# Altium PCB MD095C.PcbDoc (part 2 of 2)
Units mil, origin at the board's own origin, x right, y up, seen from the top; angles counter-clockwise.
Board outline 4500 x 5500 mil, 6 copper layers (Top Layer, Kelvin, MidLayer2, GND, InternalPlane2, Bottom Layer); 145 components, 65 nets, 384 pads, 258 vias.
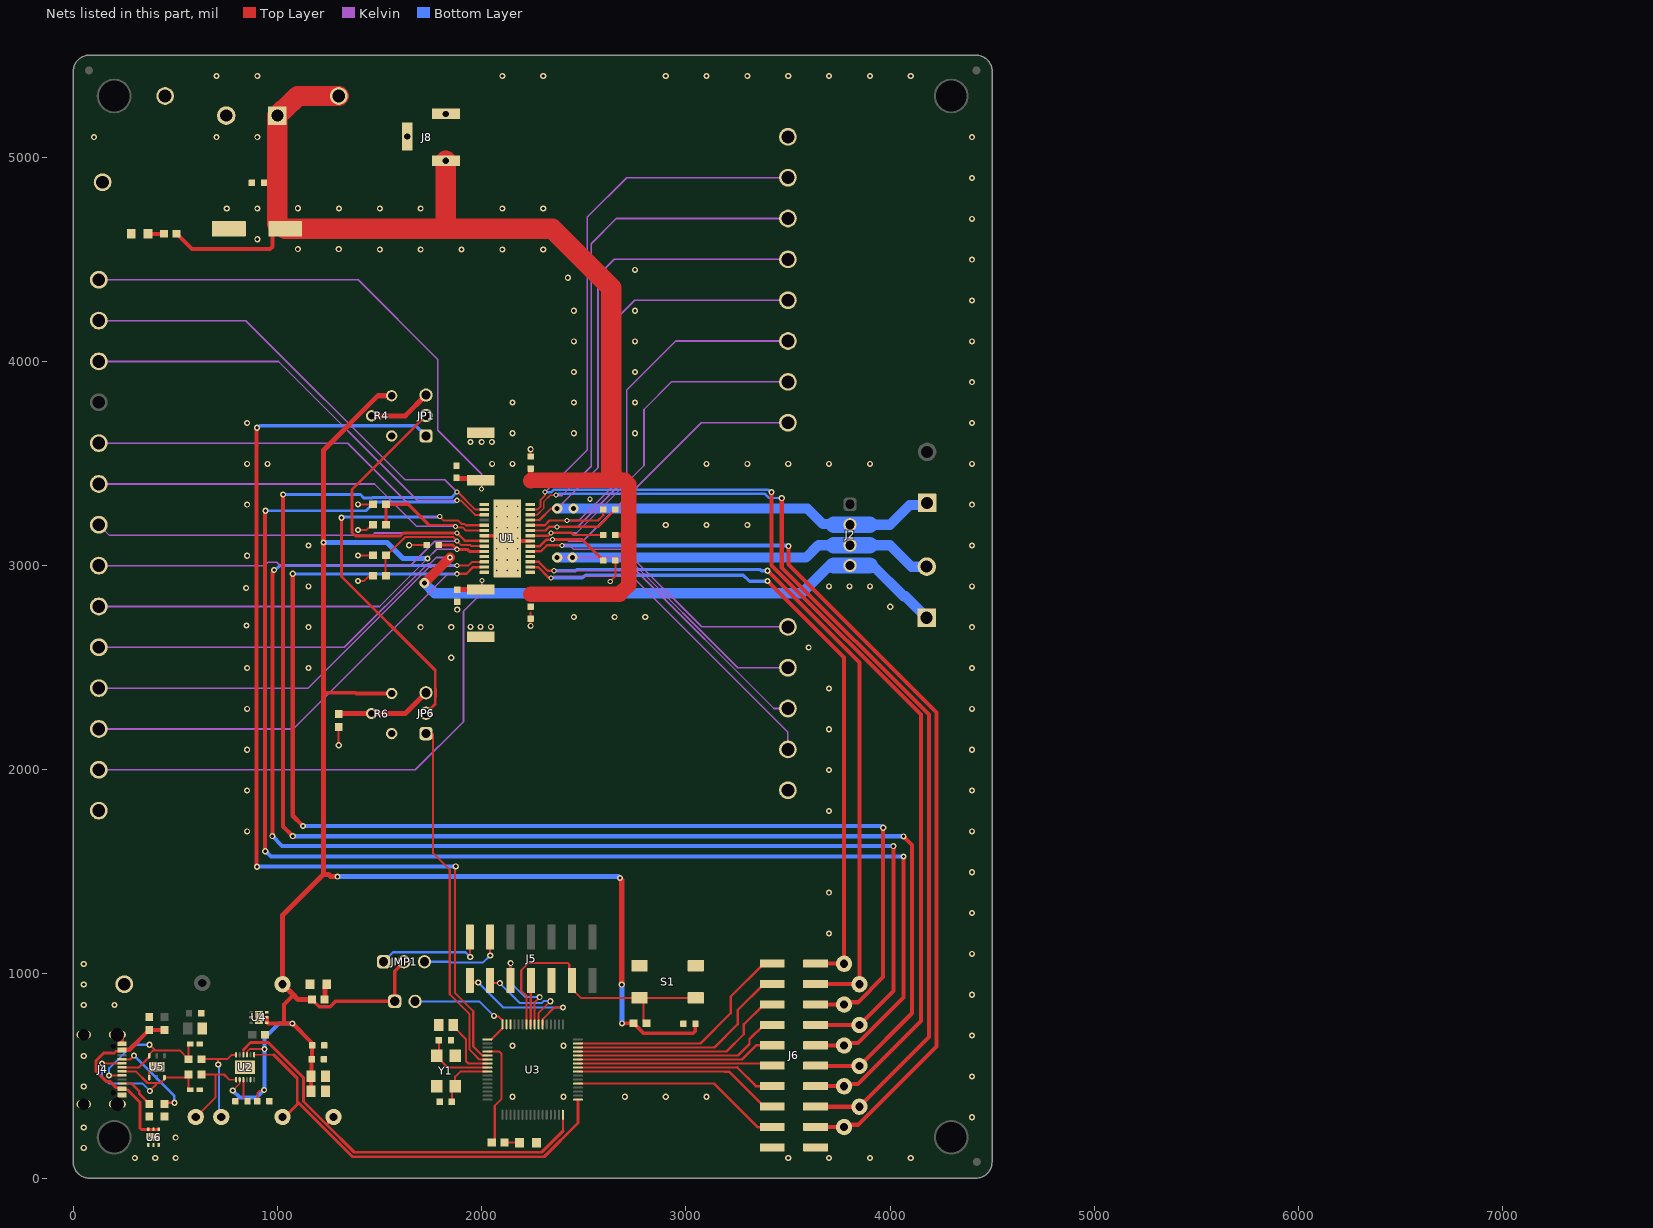
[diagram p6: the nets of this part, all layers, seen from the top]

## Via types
v1: diameter 30, hole 16, Top Layer to Bottom Layer, tented both sides, 203 vias
v2: diameter 25, hole 15, Top Layer to Bottom Layer, tented both sides, 22 vias
v3: diameter 19.68, hole 7.87, Top Layer to Bottom Layer, tented both sides, 15 vias
v4: diameter 19.68, hole 7.87, Top Layer to Bottom Layer, 12 vias
v5: diameter 50, hole 25, Top Layer to Bottom Layer, tented both sides, 6 vias

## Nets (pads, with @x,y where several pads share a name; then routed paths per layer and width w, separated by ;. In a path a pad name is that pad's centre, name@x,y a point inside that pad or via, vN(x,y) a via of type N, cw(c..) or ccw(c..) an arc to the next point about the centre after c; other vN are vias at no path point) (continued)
AOUT2: J2.2 J3.1 TP20.1 U1.25 | length 4235.3
  Top Layer w10: U1.25@2240.16,3223.23 2283.23,3223.23 2340,3280 v5(2370,3280)
  Kelvin w8: v5(2370,3280) 2570,3480 2570,4420 2650,4500 TP20.1@3500,4500
  Bottom Layer w50: v5(2370,3280) v5(2450,3280) 3595,3280 3671.74,3203.26 3720.23,3203.26 ; 3900,3200.26 4000.26,3200.26 4096.68,3296.68 4178.25,3296.68 J3.1@4192.94,3311.37
  Bottom Layer w80: 3725,3200.26 J2.2@3804.37,3200.26 3900,3200.26
BOUT1: J2.4 J7.1 TP9.1 U1.11 | length 4688.1
  Top Layer w10: U1.11@1995.91,3040 U1.11@2000,3044.09
  Top Layer w50: v5(1720,2915) v1(1845,3040)
  Kelvin w8: TP9.1@125,2600 1327.37,2600 1735.37,3008 1746.18,3008 1778.18,3040 v1(1845,3040)
  Bottom Layer w50: v5(1720,2915) 1770,2865 3567.21,2865 3702.47,3000.26 ; 3916.55,3000.26 4066.8,2850 4074.6,2850 J7.1@4179.79,2744.81
  Bottom Layer w80: 3725,3000.26 3900,3000.26
BOUT2: J2.3 J7.2 TP15.1 U1.18 | length 3232.1
  Kelvin w8: v5(2370,3040) v5(2445,3040) 2714.75,3040 3254.75,2500 TP15.1@3500,2500
  Bottom Layer w50: v5(2370,3040) v5(2445,3040) 3589,3040 3649.26,3100.26 3725,3100.26 ; 3900,3100.26 3999.74,3100.26 4105.19,2994.81 J7.2@4179.79,2994.81
  Bottom Layer w80: 3725,3100.26 J2.3@3804.37,3100.26 3900,3100.26
CC1: J4.A5 R13.1 | length 431.1
  Top Layer w10: J4.A5@238.23,581.9 278.87,581.9
  Top Layer w12: 278.87,581.9 297.02,600.04 v1(297.54,600.04) ; R13.1@446.5,364.18 451.84,369.53 v1(495.88,369.53)
  Bottom Layer w12: v1(297.54,600.04) 495.06,402.53 495.06,370.35 v1(495.88,369.53)
CC2: J4.B5 R14.1 | length 182.1
  Top Layer w10: J4.B5@238.23,463.79 284.77,463.79
  Top Layer w12: 284.77,463.79 322.19,426.37 322.19,414.48 371.5,365.17 R14.1@371.5,364.18
CP1: C7.2 TP19.1 U1.23 | length 2216.3
  Top Layer w12: U1.23@2240.16,3172.05 2312.5,3172.05 2330.46,3190 v2(2370,3190) 2370.5,3189.5 2569.03,3189.5 C7.2@2654.53,3275
  Kelvin w8: v2(2370,3190) 2470,3190 2710,3430 2710,3860 2950,4100 TP19.1@3500,4100
CP2: C7.1 TP18.1 U1.24 | length 2404.5
  Top Layer w12: U1.24@2240.16,3197.64 2309.81,3197.64 2333.07,3220.9 v2(2418.13,3220.9) 2569.9,3220.9 2595.47,3246.47 C7.1@2595.47,3275
  Kelvin w8: v2(2418.13,3220.9) 2475.9,3220.9 2650,3395 2650,4200 2750,4300 TP18.1@3500,4300
D+: C26.1 J4.A6 J4.B6 R16.1 U5.3 | length 849.9
  Top Layer w10: v1(175.52,502.41) 175.89,502.79 237.86,502.79 J4.B6@238.23,503.16 ; J4.A6@238.23,542.53 322.13,542.53 370.46,590.86 370.46,597.75 U5.3@371.7,598.98 372.93,600.22 372.93,607.11 391.38,625.56 401.15,625.56 401.35,625.76 ; v1(373.74,653.38) 401.35,625.76 ; C26.1@572.88,657.69 571.81,657.69 565,650.87 R16.1@565,582.69 564.02,582.69 520.94,625.76 401.35,625.76
  Bottom Layer w10: v1(175.52,502.41) 175.52,538.36 290.54,653.38 v1(373.74,653.38)
D-: C27.1 J4.A7 J4.B7 R15.1 U5.6 | length 927.3
  Top Layer w10: v1(140.32,561.93) 140.47,562.07 238.09,562.07 J4.B7@238.23,562.21 ; J4.A7@238.23,522.84 306.8,522.84 363.54,466.11 404.8,466.11 405,465.91 ; v1(374.97,427.47) 405,457.5 405,465.91 ; C27.1@572.88,432.69 571.81,432.69 565,439.5 R15.1@565,507.69 564.02,507.69 549.02,492.69 U5.6@446.5,492.69 445.26,491.45 445.26,484.56 426.61,465.91 405,465.91
  Bottom Layer w10: v1(140.32,561.93) 140.32,498.01 175.59,462.74 339.7,462.74 v1(374.97,427.47)
DECAY: JP6.2 TP5.1 U1.5 | length 3692.7
  Top Layer w10: v2(1795,3240) 1815,3220 1886,3220 1901.2,3204.8 1915.2,3204.8 1922.36,3197.64 U1.5@2000,3197.64
  Top Layer w14: v1(1314.1,3234.68) 1314.1,2946.9 1773.05,2487.95 1773.05,2398.59 1774.85,2396.79 1774.85,2357.62 1773.05,2355.82 1773.05,2322.68 JP6.2@1727.57,2277.2
  Kelvin w8: TP5.1@125,3600 1345,3600 1705,3240 v2(1795,3240)
  Bottom Layer w14: v1(1314.1,3234.68) 1316.76,3237.34 1792.34,3237.34 v2(1795,3240)
DIR: J6.10 TP3.1 TP41.1 U1.3 | length 9170.6
  Top Layer w10: v2(1880,3320) 1880.78,3319.22 1897.87,3319.22 1968.26,3248.82 U1.3@2000,3248.82
  Top Layer w20: v1(940,1601) 940,3268 v1(941,3269) ; J6.10@3636,651 3657,651 3657.5,650.5 3774.5,650.5 TP41.1@3775,650 3786.48,661.48 3843.5,661.48 4066.55,884.53 v1(4066.55,1575)
  Kelvin w8: TP3.1@125,4000 1005,4000 1685,3320 v2(1880,3320)
  Bottom Layer w14: v1(941,3269) 1434,3269 1476,3311 1868.02,3311 1877.02,3320 v2(1880,3320)
  Bottom Layer w20: v1(940,1601) 942.71,1601 968.71,1575 v1(4066.55,1575)
ENABLEN: J6.16 TP21.1 TP44.1 U1.26 | length 7270.5
  Top Layer w8: U1.26@2240.16,3248.82 2271.89,3248.82 2305,3281.93 2305,3313.66 2336.5,3345.16 2364.16,3345.16 v2(2365,3346)
  Top Layer w20: v1(3469.72,3330.33) 3469.72,2991.55 4190.77,2270.5 4190.77,690.77 TP44.1@3850,350 3658,350 3657,351 J6.16@3636,351
  Kelvin w8: v2(2365,3346) 2367.5,3343.5 2393.5,3343.5 2537,3487 2537,4577 2660,4700 TP21.1@3500,4700
  Bottom Layer w12: v2(2365,3346) 2367.49,3348.49 2375.42,3348.49 2378.53,3351.6 3387.67,3351.6 3408.07,3331.2 3468.85,3331.2 v1(3469.72,3330.33)
GDECAY: JP6.1 U3.6 | length 1727.8
  Top Layer w10: 1762.62,2175.63 1762.62,1591.05 1843.94,1509.73 1843.94,900.71 1941,803.65 1941,629.15 1988.94,581.21 U3.6@2028.54,581.21
GND: C1.1 C2.1 C3.1 C4.1 C5.1 C6.2 C9.2 C10.2 C11.2 C12.2 C13.2 C14.2 C15.2 C16.2 C17.1 C18.2 C19.2 C20.1 C21.1 C22.2 C23.1 C24.2 C25.1 C26.2 C27.2 C28.2 C29.1 D1.1 D10.1 D11.1 J1.2 J4.1 J4.2 J4.3 J4.4 J4.A1-B12 J4.A12-B1 J5.9 J6.19 J6.20 J8.2 J8.3 R1.2 R2.2 R4.1 R5.1 R6.1 R7.1 R13.2 R14.2 S1.1 S1.2 TP23.1 TP26.1 TP27.1 TP28.1 TP29.1 TP46.1 U1.7 U1.21 U1.29@2125.8,3133.66 U2.5 U2.13 U3.62 U3.63 U4.3 U4.5 U4.7 U5.4 U5.7@409.1,545.83 U6.1 U6.2 U6.3 U6.7@393,201 Y1.2 Y1.4 | length 1007.9
  Top Layer w10: U5.4@371.7,492.69 371.7,522.21 389.41,539.93 v3(389.41,545.83) ; v1(1300,2120) 1300,2185 ; v1(1395,2925) 1425,2925 R7.1@1450,2950 ; v1(1395,3050) C13.2@1460,3050 ; v1(1395,3175) 1437,3175 C11.2@1463,3201 ; v1(1395,3300) R5.1@1460,3300 ; v1(1645,3100) C2.1@1731.47,3100 ; U1.29@2107.28,3146.46 U1.29@2132.87,3120.87 ; v1(2240,2705) C1.1@2240,2740.47 2240,2770 ; C5.1@2240,3534.53 v1(2240,3570) ; v2(2630,2923) 2654.53,2947.53 C9.2@2654.53,3025
  Top Layer w18: U1.7@2000,3146.46 U1.29@2107.28,3146.46 ; U1.29@2132.87,3120.87 U1.21@2240.16,3120.87
  Top Layer w20: J4.1@215.99,702.76 224.66,702.76 238.23,689.2 J4.A1-B12@238.23,658.67
  other v1: 301.5,98.5 401.5,98.5 501.5,98.5 3501.5,98.5 3701.5,98.5 3901.5,98.5 4101.5,98.5 51.5,148.5 501.5,198.5 51.5,248.5 4401.5,298.5 2151.5,398.5 2401.5,398.5 2701.5,398.5 2901.5,398.5 3101.5,398.5 51.5,448.5 4401.5,498.5 51.5,598.5 2151.5,648.5 2401.5,648.5 4401.5,698.5 51.5,848.5 201.5,848.5 4401.5,898.5 51.5,948.5 51.5,1048.5 4401.5,1098.5 3701.5,1198.5 4401.5,1298.5 3701.5,1398.5 4401.5,1498.5 851.5,1698.5 4401.5,1698.5 3701.5,1798.5 851.5,1898.5 4401.5,1898.5 3701.5,1998.5 851.5,2098.5 4401.5,2098.5 3701.5,2198.5 851.5,2298.5 4401.5,2298.5 3701.5,2398.5 851.5,2498.5 1151.5,2498.5 4401.5,2498.5 1851.5,2548.5 3601.5,2598.5 1151.5,2698.5 1701.5,2698.5 1851.5,2698.5 4401.5,2698.5 1945,2700 1995,2700 2045,2700 848.4,2707.23 2451.5,2748.5 2651.5,2748.5 2801.5,2748.5 1880.79,2784.3 4001.5,2798.5 846.69,2890.63 1151.5,2898.5 3701.5,2898.5 3801.5,2898.5 3901.5,2898.5 4401.5,2898.5 851.5,3048.5 1151.5,3098.5 4401.5,3098.5 2901.5,3198.5 3101.5,3198.5 3301.5,3198.5 851.5,3298.5 4401.5,3298.5 851.5,3498.5 951.5,3498.5 2051.5,3498.5 2151.5,3498.5 3101.5,3498.5 3301.5,3498.5 3501.5,3498.5 3701.5,3498.5 3901.5,3498.5 4401.5,3498.5 1945,3605 2000,3605 2050,3605 2151.5,3648.5 2451.5,3648.5 2751.5,3648.5 851.5,3698.5 4401.5,3698.5 2151.5,3798.5 2451.5,3798.5 2751.5,3798.5 4401.5,3898.5 2451.5,3948.5 2751.5,3948.5 2451.5,4098.5 2751.5,4098.5 4401.5,4098.5 2451.5,4248.5 2751.5,4248.5 4401.5,4298.5 2422.1,4409.96 2751.5,4448.5 4401.5,4498.5 1501.5,4548.5 1701.5,4548.5 1901.5,4548.5 2101.5,4548.5 2301.5,4548.5 1100,4550 1300,4550 901.5,4598.5 4401.5,4698.5 751.5,4748.5 901.5,4748.5 1301.5,4748.5 1501.5,4748.5 1701.5,4748.5 2101.5,4748.5 2301.5,4748.5 1100,4750 4401.5,4898.5 101.5,5098.5 701.5,5098.5 901.5,5098.5 4401.5,5098.5 701.5,5398.5 901.5,5398.5 2101.5,5398.5 2301.5,5398.5 2901.5,5398.5 3101.5,5398.5 3301.5,5398.5 3501.5,5398.5 3701.5,5398.5 3901.5,5398.5 4101.5,5398.5
  other v2: 2530,3325.3
  other v3: 371.35,201 414.65,201 428.78,545.83 2074.61,2976.18 2125.8,2976.18 2176.98,2976.18 2125.8,3027.36 2125.8,3082.48 2125.8,3133.66 2125.8,3184.84 2125.8,3239.96 2074.61,3291.14 2125.8,3291.14 2176.98,3291.14
  other v4: 909.39,765.94 909.39,809.24 2074.61,3027.36 2176.98,3027.36 2074.61,3082.48 2176.98,3082.48 2074.61,3133.66 2176.98,3133.66 2074.61,3184.84 2176.98,3184.84 2074.61,3239.96 2176.98,3239.96
GVREF: JP1.1 U3.5 | length 4986.5
  Top Layer w10: v1(1873.05,1527.31) 1870.63,1524.88 1870.63,906.26 1959,817.88 1959,645.1 2003.12,600.98 2028.46,600.98 U3.5@2028.54,600.9
  Top Layer w20: v1(900,1525) 897,1528 897,3672 v1(900,3675)
  Bottom Layer w15: v1(900,3675) 904.06,3675 914.06,3685 1677.76,3685 JP1.1@1727.57,3635.19
  Bottom Layer w20: v1(900,1525) 901.15,1526.15 1871.9,1526.15 v1(1873.05,1527.31)
HOME: J6.12 TP2.1 TP42.1 U1.2 | length 9275
  Top Layer w10: v2(1880,3360) 1884.04,3360 1969.63,3274.41 U1.2@2000,3274.41
  Top Layer w20: v1(1028,3348) 1028,1722 v1(1075,1675) ; J6.12@3636,551 3657,551 3658,550 TP42.1@3850,550 4107.75,807.75 4107.75,1632.25 v1(4066,1674)
  Kelvin w8: TP2.1@125,4200 845,4200 1625,3420 1820,3420 v2(1880,3360)
  Bottom Layer w14: v1(1028,3348) 1406.18,3348 1422.18,3332 1466.17,3332 1466.97,3332.8 1852.8,3332.8 v2(1880,3360)
  Bottom Layer w20: v1(1075,1675) 1075.5,1674.5 4065.5,1674.5 v1(4066,1674)
ISENA: C6.1 R1.1 TP1.1 U1.1 | length 2668.1
  Top Layer w25: C6.1@1876.74,3429.44 1879.99,3426.19 1987.67,3426.19 R1.1@1995,3418.86
  Kelvin w8: TP1.1@125,4400 1395,4400 1785.7,4009.3 1785.7,3662.3 2000.22,3447.78 v2(2000.22,3375.21)
ISENB: C10.1 R2.1 TP12.1 U1.14 | length 2727.3
  Top Layer w25: C10.1@1880.11,2882.16 1880.6,2882.65 1994.51,2882.65 R2.1@1995,2883.14
  Kelvin w8: TP12.1@125,2000 1675,2000 1911,2236 1911,2776 2001.09,2866.09 v2(2001.09,2926.97)
MSP_DIR: J6.9 U3.43 | length 980.9
  Top Layer w10: U3.43@2471.46,581.21 3275.24,581.21
  Top Layer w12: 3275.24,581.21 3344.02,650 3422.4,650 J6.9@3423.4,651
MSP_ENABLEn: J6.15 U3.40 | length 1022.8
  Top Layer w10: U3.40@2471.46,522.16 3189.92,522.16
  Top Layer w12: 3189.92,522.16 3210.91,522.16 3382.06,351 J6.15@3423.4,351
MSP_HOME: J6.11 U3.42 | length 956.3
  Top Layer w10: U3.42@2471.46,561.53 3412.87,561.53 J6.11@3423.4,551
MSP_RESETn: J6.3 U3.46 | length 1120.9
  Top Layer w10: U3.46@2471.46,640.27 3140.06,640.27
  Top Layer w12: 3140.06,640.27 3254.22,754.43 3254.22,823.16 3382.06,951 J6.3@3423.4,951
MSP_SLEEPn: J6.13 U3.41 | length 970.2
  Top Layer w10: U3.41@2491.06,541.84 2871.3,541.84 2871.61,542.16 3251.84,542.16
  Top Layer w12: 3251.84,542.16 3343,451 J6.13@3423.4,451
MSP_SRn: J6.1 U3.47 | length 1161.1
  Top Layer w10: U3.47@2471.46,659.95 3071.59,659.95
  Top Layer w12: 3071.59,659.95 3219.98,808.35 3219.98,888.92 3382.06,1051 J6.1@3423.4,1051
MSP_STEP: J6.17 U3.37 | length 1040.6
  Top Layer w10: U3.37@2471.46,463.1 3138.78,463.1
  Top Layer w12: 3138.78,463.1 3351.89,250 3422.4,250 J6.17@3423.4,251
MSP_USM0: J6.5 U3.45 | length 1075.3
  Top Layer w10: U3.45@2471.46,620.58 3199.38,620.58
  Top Layer w12: 3199.38,620.58 3283.88,705.08 3283.88,752.82 3382.06,851 J6.5@3423.4,851
MSP_USM1: J6.7 U3.44 | length 1027.8
  Top Layer w10: U3.44@2471.46,600.9 3255.27,600.9
  Top Layer w12: 3255.27,600.9 3311.82,657.45 3311.82,680.76 3382.06,751 J6.7@3423.4,751
NetC12_1: C12.1 JP6.3 R6.2 | length 469.3
  Top Layer w25: C12.1@1300,2275 1300.32,2275.32 1460.1,2275.32 R6.2@1460.42,2275 ; R6.2@1461.06,2275.64 1626,2275.64 JP6.3@1727.57,2377.2
NetC20_2: C20.2 U3.8 Y1.1 | length 355
  Top Layer w10: C20.2@1790.94,675 1790.94,611.02 Y1.1@1779.72,599.8 1779.72,595.87 1833.75,541.84 U3.8@2028.54,541.84
NetC21_2: C21.2 U3.9 Y1.3 | length 297
  Top Layer w10: C21.2@1854.53,375 1854.53,434.45 Y1.3@1870.28,450.2 1870.28,496.69 1895.74,522.16 U3.9@2028.54,522.16
NetC25_2: C25.2 U2.3 | length 113.8
  Top Layer w9: U2.3@833.06,482.34 833.06,397.19 C25.2@853.32,376.93
NetD1_2: D1.2 R3.2 | length 77.2
  Top Layer w20: D1.2@366.34,4625 R3.2@443.5,4625
NetD10_2: D10.2 R9.1 | length 73.7
  Top Layer w10: R9.1@2112.5,175 2183.32,175 D10.2@2185.32,173
NetD11_2: D11.2 R10.1 | length 78.7
  Top Layer w25: R10.1@1232.48,875 1232.48,941.14 D11.2@1241.34,950
NetJ5_2: J5.2 JMP1.1 | length 551.6
  Top Layer w12: J5.2@1942,1181 1943,1180 1943,1084 v1(1944,1083)
  Bottom Layer w12: JMP1.1@1520,1060 1566.28,1106.28 1920.61,1106.28 1943.89,1083 v1(1944,1083)
NetJ5_4: J5.4 JMP1.3 | length 429
  Top Layer w10: v1(2042,1090.75) J5.4@2042,1181
  Bottom Layer w10: JMP1.3@1720,1060 1848.05,1060 1852.85,1055.2 2006.45,1055.2 v1(2042,1090.75)
NetJP1_3: JP1.3 R4.2 | length 308.6
  Top Layer w25: R4.2@1461.06,3733.63 1626,3733.63 JP1.3@1727.57,3835.19
NetJP7_2: JP7.2 U3.1 U3.64 | length 543.3
  Top Layer w10: U3.1@2048.15,679.72 U3.64@2102.28,733.85 ; v1(2060.07,794.86) 2063.9,791.04 2084.31,791.04 U3.64@2102.28,773.06
  Bottom Layer w10: JP7.2@1674,866 1988.93,866 v1(2060.07,794.86)
P6M5: R9.2 U3.4 | length 527.9
  Top Layer w10: U3.4@2028.54,620.58 2085.29,620.58 2097.62,608.25 2097.62,388.6 2064.19,355.17 2064.19,188.7 2050.49,175 R9.2@2049.5,175
RCA: C11.1 R5.2 TP6.1 U1.6 | length 2455.6
  Top Layer w10: 1740,3200 1865,3200 1878,3187 1907.83,3187 1922.78,3172.05 U1.6@2000,3172.05
  Top Layer w16: C11.1@1531.5,3200 R5.2@1531.5,3300 1640,3300 1740,3200
  Kelvin w8: TP6.1@125,3400 1475,3400 1682.96,3192.04 v2(1872.96,3192.04)
RCB: C13.1 R7.2 TP8.1 U1.9 | length 2447.7
  Top Layer w10: R7.2@1530,2944 1530,3045 1625,3140 1860,3140 v2(1880,3120) 1899.7,3100.3 1945.25,3100.3 1950.28,3095.28 U1.9@2000,3095.28
  Kelvin w8: TP8.1@125,3000 936.82,3000 953.82,3017 996.18,3017 1013.18,3000 1650,3000 1770,3120 v2(1880,3120)
RESETN: J6.4 TP14.1 TP38.1 U1.17 | length 5032.4
  Top Layer w12: U1.17@2240.16,3018.5 2279.5,3018.5 2323,2975 v2(2355,2975)
  Top Layer w20: v1(3400,2975) 3850,2525 TP38.1@3850,950 3658,950 3657,951 J6.4@3636,951
  Kelvin w8: v2(2355,2975) 2757.12,2975 3432.12,2300 TP14.1@3500,2300
  Bottom Layer w15: v2(2355,2975) 2460,2975 2465,2980 3365,2980 3370,2975 v1(3400,2975)
RST: J5.11 R8.2 S1.3 S1.4 U3.58 | length 1418
  Top Layer w10: U3.58@2220.47,753.46 2220.47,892.27 2194,918.74 2194,1018.06 2228.94,1053 2423.34,1053 2429.2,1047.14 2429.2,981.2 J5.11@2442,968.4 2442,927.06 2485.8,883.26 S1.3@2773.2,883.26 ; R8.2@2807.5,758 2806.51,758 2792.81,771.7 2792.81,863.65 S1.3@2773.2,883.26 ; S1.4@3048.8,883.26 S1.3@2773.2,883.26
RX: TP35.1 U2.10 U3.32 | length 2049.8
  Top Layer w9: U2.10@833.06,612.18 833.06,628.76
  Top Layer w10: 2397.64,229.64 U3.32@2397.64,292.94
  Top Layer w14: 833.06,628.76 868.3,664 955,664 1127.13,491.87 1127.13,376.17 1239.65,263.65 ; TP35.1@1268.13,300 TP35.1@1275,300 1275,299 1239.65,263.65 ; 2397.64,229.64 2294.8,126.8 1376.5,126.8 1239.65,263.65
SLEEPN: J6.14 TP22.1 TP43.1 U1.27 | length 7291.2
  Top Layer w10: U1.27@2240.16,3274.41 2273.31,3274.41 2288,3289.1 2288,3320.7 2310,3342.7 v2(2310,3360)
  Top Layer w20: v1(3420,3360) 3420,3001.67 4151,2270.67 4151,768.98 3843.5,461.48 3786.48,461.48 TP43.1@3775,450 3774.5,450.5 3657.5,450.5 3657,451 J6.14@3636,451
  Kelvin w8: v2(2310,3360) 2518,3568 2518,4708 2710,4900 TP22.1@3500,4900
  Bottom Layer w12: v2(2310,3360) 2341.81,3360 2354.11,3372.3 3402.83,3372.3 3415.13,3360 v1(3420,3360)
SRN: J6.2 TP13.1 TP37.1 U1.16 | length 4932.3
  Top Layer w12: U1.16@2240.16,2992.91 2277.09,2992.91 2327.51,2942.49 2337.51,2942.49 v2(2340,2940)
  Top Layer w20: v1(3400,2925) 3775,2550 TP37.1@3775,1050 3774.5,1050.5 3657.5,1050.5 3657,1051 J6.2@3636,1051
  Kelvin w8: v2(2340,2940) 2344.6,2940 2351.9,2947.3 2736.7,2947.3 3500,2184 TP13.1@3500,2100
  Bottom Layer w15: v2(2340,2940) 2495,2940 2508,2953 3282,2953 3311.5,2923.5 v1@3400,2923.5
STEP: J6.18 TP16.1 TP45.1 U1.19 | length 6054.1
  Top Layer w12: U1.19@2240.16,3069.68 2289.68,3069.68 2319.5,3099.5 v2(2394,3099.5)
  Top Layer w20: v1(3502.72,3095.39) 3502.72,3006.56 4227.66,2281.61 4227.66,645.64 3843.5,261.48 3786.48,261.48 TP45.1@3775,250 3774.5,250.5 3657.5,250.5 3657,251 J6.18@3636,251
  Kelvin w8: v2(2394,3099.5) 2430.5,3099.5 2450,3080 2697.37,3080 3077.37,2700 TP16.1@3500,2700
  Bottom Layer w20: v2(2394,3099.5) 3491.54,3099.5 3493.73,3097.31 3500.81,3097.31 v1(3502.72,3095.39)
TCK: J5.7 U3.57 | length 232.1
  Top Layer w10: U3.57@2240.16,753.46 2240.16,745.63 2240.52,745.27 2240.52,966.92 J5.7@2242,968.4
TDI/TCLK: J5.3 U3.55 | length 460.9
  Top Layer w10: J5.3@2042,968.4 2055.4,955 v1(2089.25,955) ; U3.55@2279.53,773.06 2279.53,809.65 v1(2336.66,866.78)
  Bottom Layer w10: v1(2089.25,955) 2185.62,858.62 2295.77,858.62 2303.93,866.78 v1(2336.66,866.78)
TDO/TDI: J5.1 U3.54 | length 658.9
  Top Layer w10: J5.1@1942,968.4 1952.17,958.23 v1(1983.47,958.23) ; U3.54@2299.21,753.46 2299.29,753.54 2299.29,778.88 2356.15,835.74 v1(2398.13,835.74)
  Bottom Layer w10: v1(1983.47,958.23) 2105.96,835.74 v1(2398.13,835.74)
TMS: J5.5 U3.56 | length 495.1
  Top Layer w10: J5.5@2142,968.4 v1(2142,1053.25) ; U3.56@2259.84,753.46 2259.84,862.01 v1(2284.26,886.42)
  Bottom Layer w10: v1(2142,1053.25) 2142,958 2213.58,886.42 v1(2284.26,886.42)
TX: TP34.1 U2.7 U3.33 | length 2151
  Top Layer w9: U2.7@886.21,604.39 981.61,604.39
  Top Layer w14: 981.61,604.39 1097,489 1097,375.47 ; TP34.1@1025,300 1035.58,300 1097,361.42 1097,375.47 ; U3.33@2471.46,382.28 2471.46,269.46 2307,105 1367.47,105 1097,375.47
USB5V: C14.1 J4.A4-B9 J4.A9-B4 L1.1 U6.4 U6.5 U6.6 | length 950.6
  Top Layer w12: 189.18,612.88 200.32,612.88 208.81,621.36 232.42,621.36 J4.A4-B9@238.23,627.17
  Top Layer w14: 189.18,612.88 149.13,612.88 110.52,574.27 110.52,525.27 163.17,472.61 181.07,472.61 210.6,443.08 211.15,443.08 211.22,443.01 233.42,443.01 J4.A9-B4@238.23,438.2 243.04,433.39 265.75,433.39 326,373.13 326,246.2 334.2,238 417.5,238 418.59,239.09 U6.4@418.59,239.39
  Top Layer w20: J4.A4-B9@238.23,627.17 240.04,628.98 275.28,628.98 371.5,725.2 C14.1@371.5,726.19 L1.1@446.5,726.19
USBDM: R15.2 TP33.1 U2.1 | length 428.8
  Top Layer w9: 763.53,482.34 U2.1@797.63,482.34
  Top Layer w10: TP33.1@600,300 602,300 696,394 696,507.69 ; R15.2@627.99,507.69 696,507.69 ; 763.53,482.34 738.18,507.69 696,507.69
USBDP: R16.2 TP36.1 U2.12 | length 467.2
  Top Layer w9: 775.25,603.76 U2.12@797.63,603.76
  Top Layer w10: R16.2@627.99,582.69 709,582.69 ; v1@709,557 709,582.69 ; 775.25,603.76 754.18,582.69 709,582.69
  Bottom Layer w10: v1(710.17,557) 714,553.17 714,311 TP36.1@725,300
USM0: J6.6 TP11.1 TP39.1 U1.13 | length 8229.4
  Top Layer w12: v2(1880,2960) 1925,2960 1957.91,2992.91 U1.13@2000,2992.91
  Top Layer w20: v1(1075,2960) 1075,1775 v1(1125,1725) ; J6.6@3636,851 3657,851 3657.5,850.5 3774.5,850.5 TP39.1@3775,850 3786.48,861.48 3843.5,861.48 3966.71,984.68 v1(3966.71,1716.47)
  Kelvin w8: TP11.1@125,2200 1077.33,2200 1762,2884.67 1762,2887 1835,2960 v2(1880,2960)
  Bottom Layer w15: v1(1075,2960) v2(1880,2960)
  Bottom Layer w20: v1(1125,1725) 3955.47,1725 3964,1716.47 v1(3966.71,1716.47)
USM1: J6.8 TP10.1 TP40.1 U1.12 | length 8564.3
  Top Layer w10: v2(1880,3000) 1935,3000 1953.5,3018.5 U1.12@2000,3018.5
  Top Layer w20: v1(975,1675) 975,2966.92 983.9,2975.82 v1(983.9,2978.52) ; J6.8@3636,751 3657,751 3658,750 TP40.1@3850,750 4016.27,916.27 v1(4016.27,1626.09)
  Kelvin w8: TP10.1@125,2400 1150,2400 1742,2992 1752.81,2992 1760.81,3000 v2(1880,3000)
  Bottom Layer w15: v1(983.9,2978.52) 989.11,2978.52 1010.59,3000 v2(1880,3000)
  Bottom Layer w20: v1(975,1675) 1022.2,1627.8 4014.56,1627.8 v1(4016.27,1626.09)
V3P3: C2.2 C15.1 C16.1 C17.2 C22.1 C23.2 C28.1 JMP1.2 JP7.1 R4.3 R6.3 R8.1 R10.2 TP25.1 TP32.1 U1.10 U2.2 U2.9 U4.1 U4.2 | length 11076.1
  Top Layer w9: v1(780.81,429.42) 815.18,463.79 815.18,482.18 U2.2@815.34,482.34 ; U2.9@850.78,604.39 850.94,604.55 850.94,619.34 864.13,632.53 936.47,632.53 v1(937.11,631.89) ; C28.1@901.59,376.93 901.59,415.94 913.45,427.81 930.7,427.81 v1(934.72,431.83)
  Top Layer w15: C2.2@1790.53,3100 1860,3100 v2(1880,3080) 1929.37,3080 1939.68,3069.68 U1.10@2000,3069.68
  Top Layer w18: R10.2@1168.5,875 1169.49,875 1192.12,852.36 1192.12,852.23 1204.85,839.5 1258.14,839.5 1284.64,866 JP7.1@1574,866 1574,1014 JMP1.2@1620,1060 ; 1225,2377.58 1381.59,2377.58 1385.74,2373.43 R6.3@1566.5,2373.43 ; v1(2687.93,758.16) 2688.01,758.08 2744.42,758.08 R8.1@2744.5,758 2745.49,758 2770.81,732.68 2770.81,732.26 2792.81,710.26 3036.15,710.26 3046.69,720.81 3046.69,750.25 3047.53,751.09 C15.1@3047.53,757
  Top Layer w20: U4.2@947.77,787.59 U4.1@947.77,762 952.79,756.99 1033,756.99 ; v1(1073,756.99) 1033,756.99 ; v1@1074.91,757.09 1164.72,667.28 1164.72,655.75 C23.2@1170.47,650 1169.55,649.08 1169.55,583.3 C17.2@1168.64,582.38 1166.6,580.34 1166.6,500 1164.57,497.96 C16.1@1164.57,425 ; 1078.5,896.5 1033,851 1033,756.99
  Top Layer w25: R10.2@1168.5,875 1100,875 1078.5,896.5 TP32.1@1025,950 1025,1288.03 1225,1488.03 ; v1(1294.47,1476.57) 1293.52,1477.53 1260.5,1477.53 1250,1488.03 1225,1488.03 ; R4.3@1559.48,3832.05 1491.8,3832.05 1225,3565.25 v1(1225,3113) 1225,2377.58 1225,1488.03 ; v1(2677.26,1470.31) 2677.26,1468.96 2686.35,1459.87 v1(2686.35,947.8)
  Kelvin w8: TP25.1@125,2800 1500,2800 v1(1735,3035) 1780,3080 v2(1880,3080)
  Bottom Layer w20: v1(780.81,429.42) 815.61,394.61 897.5,394.61 v1(934.72,431.83) 935.92,433.02 935.92,627.27 v1@934.78,628.4 ; v1(937.11,631.89) 937.11,687.33 1006.77,756.99 v1(1073,756.99)
  Bottom Layer w25: v1(1225,3113) 1537,3113 1615,3035 v1(1735,3035) ; v1(1294.47,1476.57) 2669.64,1476.57 2675.91,1470.31 v1(2677.26,1470.31) ; v1(2686.35,947.8) 2687.14,947.01 2687.14,758.95 v1(2687.93,758.16)
VCP: C8.2 TP17.1 U1.22 | length 1992.7
  Top Layer w12: U1.22@2240.16,3146.46 2326.46,3146.46 v2(2340,3160) 2440,3160 2450,3150 C8.2@2595.47,3150
  Kelvin w8: v2(2340,3160) 2465,3160 2795,3490 2795,3765 2930,3900 TP17.1@3500,3900
VGD: C9.1 TP30.1 U1.20 | length 1810.6
  Top Layer w12: U1.20@2240.16,3095.28 2285.28,3095.28 2316.14,3126.14 2345.11,3126.14 v2(2346.64,3127.68) v2@2344.82,3129.49
  Top Layer w14: v2(2346.64,3127.68) 2492.8,3127.68 C9.1@2595.47,3025
  Kelvin w8: v2(2346.64,3127.68) 2419.28,3127.68 2426.96,3120 2495,3120 3075,3700 TP30.1@3500,3700
VM: C1.2 C3.2 C4.2 C5.2 C8.1 J1.1 J8.1 R3.1 TP24.1 U1.15 U1.28 | length 6209.1
  Top Layer w20: R3.1@506.5,4625 507.48,4625 582.48,4550 963.28,4550 975,4561.72 975,4622.6 1002.4,4650 C4.2@1037.8,4650 ; C3.2@929.53,4875 C3.2@934.06,4875 1000,4875
  Top Layer w25: C5.2@2240,3475.47 2240,3421 2243,3418 ; C8.1@2654.53,3150 2710,3150 2720,3160
  Top Layer w75: 2240,2860 2676.07,2860 2720,2903.93 2720,3160 2720,3400 2702,3418 2678.67,3418 ; 2240,3415 2243,3418 2678.67,3418 ; 2635,3461.67 2678.67,3418 ; 2635,3875 2640,3870
  Top Layer w100: J1.1@999.19,5204.04 1024.35,5229.2 1029.33,5229.2 1100.13,5300 TP24.1@1300,5300 ; C4.2@1000,4674.9 1000,4875 J1.1@1000,5204.04 ; C4.2@1037.8,4650 1825,4650 ; J8.1@1825,4983.65 1825,4650 ; 2635,3461.67 2635,3875 2635,4360 2345,4650 1825,4650
VREF: JP1.2 TP7.1 U1.8 | length 3168.5
  Top Layer w12: v2(1880,3160) 1918,3122 1998.87,3122 U1.8@2000,3120.87
  Top Layer w14: JP1.2@1727.57,3735.19 1365.2,3372.83 1365.2,3162.66 1382.66,3145.2 1602.2,3145.2 1617,3160 v2(1880,3160)
  Kelvin w8: TP7.1@125,3200 177,3148 1463,3148 1475,3160 v2(1880,3160)
VREF+: C18.1 U3.7 | length 312.6
  Top Layer w10: C18.1@1860.43,750 1860.43,744.09 1923,681.53 1923,574 1935.47,561.53 U3.7@2028.54,561.53
pads on no net: FID1.1 FID2.1 FID3.1 H9.0 H10.0 H11.0 H12.0 J4. J4.A8 J4.B8 J5.6 J5.8 J5.10 J5.12 J5.13 J5.14 LBL1.0 SH-J1.0 SH-J2.0 SH-J3.0 SH-J4.0 SH-J5.0 SH-J6.0 SH-J7.0 SH-J8.0 SH-J9.0 SH-J10.0 SH-JMP1.0 SH-JP1.0 SH-JP6.0 SH-JP7.0 U1.29@2125.8,3133.66 U2.6 U2.8 U2.11 U3.2 U3.3 U3.10 U3.11 U3.12 U3.13 U3.14 U3.15 U3.16 U3.17 U3.18 U3.19 U3.20 U3.21 U3.22 U3.23 U3.24 U3.25 U3.26 U3.27 U3.28 U3.29 U3.30 U3.31 U3.34 U3.35 U3.36 U3.38 U3.39 U3.48 U3.49 U3.50 U3.51 U3.52 U3.53 U3.59 U3.60 U3.61 U4.4 U5.2 U5.5 U5.7@409.1,545.83 U6.7@375.28,201 U6.7@410.72,201

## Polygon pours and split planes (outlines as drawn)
GND on Top Layer "TOP-GND" (solid, remove dead copper, pour order 1008): 0,0 4500,0 4500,5500 0,5500 0,5400
BOUT1 on Top Layer "BOUT1" (solid, pour order 1000): 1825,2985 1850,3010 1935,3010 1955,3030 2040,3030 2040,3060 1940,3060 1925,3075 1845,3075 1790,3020
AOUT1 on Top Layer "AOUT1" (solid, pour order 1001): 1770,3315 1875,3210 1980,3210 2040,3210 2040,3235 1965,3235 1960,3240 1910,3290 1880,3290 1865,3290 1805,3350 1770,3315
BOUT2 on Top Layer "BOUT2" (solid, pour order 1002): 2200,3030 2290,3030 2325,2995 2515,2995 2515,3075 2315,3075 2295,3055 2200,3055
AOUT2 on Top Layer "AOUT2" (solid, pour order 1003): 2200,3210 2360,3210 2395,3245 2485,3245 2485,3315 2340,3315 2265,3240 2200,3240
VM on Top Layer "VMA" (solid, remove dead copper, pour order 1004): 2200,2790 2200,2980 2315,2980 2315,2825 2280,2790
ISENB on Top Layer "ISENB" (solid, pour order 1005): 1930,2860 1930,2945 1960,2975 2061.9,2975 2061.9,2860
ISENA on Top Layer "ISENA" (solid, pour order 1006): 2035,3290 2035,3330 2045,3340 2061.38,3356.38 2061.38,3450 1925,3450 1925,3330 1965,3290
GND on Kelvin "KLV-GND" (solid, remove dead copper, pour order 1010): 0,0 4500,0 4500,5500 0,5500 0,0
GND on Bottom Layer "BOT-GND" (solid, remove dead copper, pour order 1009): 0,0 4500,0 4500,5500 0,5500 0,0
no net on InternalPlane2 (split plane): 79,5479.9 4418.62,5479.9 4421.26,5479.64 4421.84,5479.7 4427.84,5479.36 4434.33,5478.26 4440.66,5476.44 4446.74,5473.92 4452.51,5470.73 4457.88,5466.92 4462.79,5462.53 4467.18,5457.62 4470.99,5452.25 4474.18,5446.48 4476.7,5440.4 4478.52,5434.07 4479.62,5427.58 4479.96,5421.58 4479.9,5421 4479.9,81.63 4479.64,79 4479.7,78.42 4479.36,72.42 4478.26,65.93 4476.44,59.6 4473.92,53.52 4470.73,47.75 4466.92,42.38 4462.53,37.47 4457.62,33.08 4452.25,29.27 4446.48,26.08 4440.4,23.56 4434.07,21.74 4427.58,20.64 4421.58,20.3 4421,20.36 4418.36,20.1 81.38,20.1 78.74,20.36 78.16,20.3 72.16,20.64 65.67,21.74 59.34,23.56 53.26,26.08 47.49,29.27 42.12,33.08 37.21,37.47 32.82,42.38 29.01,47.75 25.82,53.52 23.3,59.6 21.48,65.93 20.38,72.42 20.04,78.42 20.1,79 20.1,5418.62 20.36,5421.26 20.3,5421.84 20.64,5427.84 21.74,5434.33 23.56,5440.66 26.08,5446.74 29.27,5452.51 33.08,5457.88 37.47,5462.79 42.38,5467.18 47.75,5470.99 53.52,5474.18 59.6,5476.7 65.93,5478.52 72.42,5479.62 78.42,5479.96
GND on GND (split plane): 79,5479.9 4418.62,5479.9 4421.26,5479.64 4421.84,5479.7 4427.84,5479.36 4434.33,5478.26 4440.66,5476.44 4446.74,5473.92 4452.51,5470.73 4457.88,5466.92 4462.79,5462.53 4467.18,5457.62 4470.99,5452.25 4474.18,5446.48 4476.7,5440.4 4478.52,5434.07 4479.62,5427.58 4479.96,5421.58 4479.9,5421 4479.9,81.63 4479.64,79 4479.7,78.42 4479.36,72.42 4478.26,65.93 4476.44,59.6 4473.92,53.52 4470.73,47.75 4466.92,42.38 4462.53,37.47 4457.62,33.08 4452.25,29.27 4446.48,26.08 4440.4,23.56 4434.07,21.74 4427.58,20.64 4421.58,20.3 4421,20.36 4418.36,20.1 81.38,20.1 78.74,20.36 78.16,20.3 72.16,20.64 65.67,21.74 59.34,23.56 53.26,26.08 47.49,29.27 42.12,33.08 37.21,37.47 32.82,42.38 29.01,47.75 25.82,53.52 23.3,59.6 21.48,65.93 20.38,72.42 20.04,78.42 20.1,79 20.1,5418.62 20.36,5421.26 20.3,5421.84 20.64,5427.84 21.74,5434.33 23.56,5440.66 26.08,5446.74 29.27,5452.51 33.08,5457.88 37.47,5462.79 42.38,5467.18 47.75,5470.99 53.52,5474.18 59.6,5476.7 65.93,5478.52 72.42,5479.62 78.42,5479.96

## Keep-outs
Keep-Out Layer:
  lines w10: 0.26,5422.26 0.26,80 ccw(c79,80) 79,1.26 ; 0.52,5422.26 cw(c79.26,5422.26) 79.26,5501 4421.52,5501 ; 79,1 4421.26,1 ; 4421.26,1.26 ccw(c4421.26,80) 4500,80 ; 4421.52,5500.74 cw(c4421.52,5422) 4500.26,5422 4500.26,80

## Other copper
Top Layer:
  rectangle net VM: 2205,3295 2275,3455
  rectangle net GND: 1925,3555 2075,3685
  text "Top Layer" at 4790,4820 h50
Kelvin:
  rectangle net GND: 2037,2942 2202,3348
  text "MidLayer1 - KELVIN" at 4800,4600 h50
MidLayer2:
  text "MidLayer2 - ALT-PWR" at 6385,4525 h50
Bottom Layer:
  text "BottomLayer" at 4800,4200 h50
GND (plane layer: these items are gaps in the copper):
  text "PLANE - GND" at 4800,4400 h50

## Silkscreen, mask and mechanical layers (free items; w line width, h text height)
Top Overlay:
  circle w10: c336,141 r5.1
  circle w14: c1972,3315 r5
  lines w5: 1669,2426 1669,2428
  lines w8: 1647,2450 1669,2428 ; 1650,3910 1672,3888 ; 1804,2447 1783,2426 ; 1807,3907 1786,3886 ; 1783,2426 1669,2426 1669,2125 1783,2125 1783,2426 ; 1786,3886 1672,3886 1672,3585 1786,3585 1786,3886 ; 1467.8,1004.57 1467.8,1118.57 1768.8,1118.57 1768.8,1004.57 1467.8,1004.57 ; 1524.8,809 1524.8,923 1725,923 1725,809 1524.8,809
  lines w10: 4790,3710 7490,3710
  lines w15: 1860,975 1860,1057 ; 1907.55,971.75 1889.05,971.75 1889.05,1177.65 1907.55,1177.65 ; 2576.45,971.75 2594.95,971.75 2594.95,1177.65 2576.45,1177.65 ; 4673,234 4673,5364 cw(c4760,5364) 4760,5451 7482,5451 cw(c7482,5364) 7569,5364 7569,234 ; 4673,235 ccw(c4760,235) 4760,148 7482,148 ccw(c7482,235) 7569,235 ; 4730,5025 7506,5025 ; 4730,5215 7506,5215
  text ".PRJ_Number_and_Rev" at 2401,5360 h60
  text "Layer Stack Up Detail for: DRV8818EVM" at 4735,5325 h50
  text "DRV8818EVM" at 2260.28,5194.32 h110
  text "8V - 35V DC" at 1193,5141 h80
  text "Layer Name" at 4740,5090 h50
  text "VM" at 75,4600 h60
  text "VREF SELECT" at 1545,3916 h60
  text "POT" at 1803,3814 h40
  text "SENSEA" at 1888.72,3699.56 h40
  text "INT" at 1803,3613 h40
  text "A1" at 3976,3546 h70 r90
  text "VREF" at 1431,3533 h40
  text "RCA" at 1444,3337 h60
  text "AOUT1" at 3525,3275 h40
  text "A2" at 3976,3222 h70 r90
  text "AOUT2" at 3525,3175 h40
  text "BOUT2" at 3525,3075 h40
  text "BOUT1" at 3525,2975 h40
  text "B2" at 3976,2958 h70 r90
  text "DRV8818" at 2076,2889 h40
  text "RCB" at 1445,2875 h60
  text "B1" at 3976,2703 h70 r90
  text "SENSEB" at 1890,2560 h40
  text "DECAY SELECT" at 1521,2453 h60
  text "POT" at 1810,2358 h40
  text "INT" at 1810,2155.27 h40
  text "DECAY" at 1415.68,2064.65 h40
  text "JTAG CONN" at 2092,1264 h40
  text "JTG PWR" at 1538,1130 h60 r90
  text "3V3" at 1643,1129 h60 r90
  text "TRG PWR" at 1744,1129 h60 r90
  text "RESET" at 2840,1113 h30
  text "SRn" at 3865,1037 h40
  text "1" at 3323,1035 h45
  text "1" at 1444,1028 h35
  text "RESETn" at 3927,935.62 h40
  text "1" at 1866,896 h45
  text "USM0" at 3863,834.25 h40
  text "MCU PWR" at 1488,764 h60
  text "USB-C" at 25.59,758.42 h50
  text "USM1" at 3927,732.88 h40
  text "DIR" at 3863,631.5 h40
  text "HOME" at 3927,530.12 h40
  text "SLEEPn" at 3863,428.75 h40
  text "ENABLEn" at 3927,327.38 h40
  text "STEP" at 3863,226 h40
  text "GND" at 3726,124 h40
  text "STATUS" at 2155,83 h30
Bottom Overlay:
  drawing of 74 lines, arcs and shapes, not listed
  text "VM" at 1371,5371 h70
  text "GND" at 551,5362 h70
  text "GND" at 847,5265 h70
  text "VM" at 1062,5265 h70
  text "GND" at 1889,5257 h50
  text "GND" at 1591,5075 h50
  text "VM" at 1869,4887 h50
  text "DRV8818EVM" at 2352,4339.96 h70
  text "A1" at 4380,3607 h70 r90
  text "A2" at 4380,3358 h70 r90
  text "AOUT1" at 3743,3282 h40
  text "AOUT2" at 3743,3182 h40
  text "BOUT2" at 3743,3082 h40
  text "B2" at 4380,3039 h70 r90
  text "BOUT1" at 3743,2982 h40
  text "B1" at 4380,2795 h70 r90
  text "DRV8818EVM  REV C 9/1/2024" at 2925,1530 h40
  text "SRn" at 3717,1043 h40
  text "GND" at 313,1031 h50
  text "5V" at 674,1031 h50
  text "3.3V" at 1110,1031 h50
  text "RESETn" at 3791,936 h40
  text "USM0" at 3717,832 h40
  text "USM1" at 3791,727 h40
  text "DIR" at 3717,634 h40
  text "HOME" at 3791,528 h40
  text "SLEEPn" at 3717,430 h40
  text "ENABLEn" at 3791,327.66 h40
  text "STEP" at 3717,228 h40
  text "D-" at 622,175 h50
  text "D+" at 764,175 h50
  text "TX" at 1067,175 h50
  text "RX" at 1315,175 h50
Mechanical 1:
  lines w10: 0,5421.26 0,79 ccw(c78.74,79) 78.74,0.26 ; 0.26,5421.26 cw(c79,5421.26) 79,5500 4421.26,5500 ; 78.74,0 4421,0 ; 4421,0.26 ccw(c4421,79) 4499.74,79 ; 4421.26,5499.74 cw(c4421.26,5421) 4500,5421 4500,79
Drill Drawing:
  text "Notes:" at 4790,3520 h60
  text "1.  NUMBER OF FINISHED LAYERS:  4" at 4790,3320 h60
  text "2.  BOARD MATERIAL AND CONSTRUCTION TO BE UL" at 4790,3120 h60
  text "APPROVED AND MARKED ON THE FINISHED BOARD." at 4990,2920 h60
  text "3.  LAMINATE MATERIAL: COPPER-CLAD FR-4" at 4790,2720 h60
  text "4.  COPPER WEIGHT: 1oz FINISHED" at 4790,2520 h60
  text "5.  FINISHED THICKNESS: .062 +/- .010" at 4790,2320 h60
  text "6.  MIN PLATING THICKNESS IN THROUGH HOLES: .001\"" at 4790,2120 h60
  text "7.  Gold Plating" at 4790,1920 h60
  text "8.  LPI SOLDERMASK BOTH SIDES USING APPROPRIATE" at 4790,1720 h60
  text "Drill Drawing." at 7700,1700 h40
  text "LAYER ARTWORK:  COLOR = RED" at 4990,1520 h60
  text ".LEGEND" at 7700,1500 h40
  text "9.  LPI SILKSCREEN AS REQUIRED:  COLOR - WHITE" at 4805,1338 h60
  text "10.  VENDOR INFORMATION TO BE INCORPORATED" at 4790,1120 h60
  text "ON BACK SIDE WHENEVER POSSIBLE" at 4990,920 h60
  text "11.  MINIMUM COPPER CONDUCTOR WIDTH IS: 8 MILS" at 4790,720 h60
  text "12. MINIMUM CONDUCTOR SPACING IS: 8 MILS" at 4790,520 h60

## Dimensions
-100,5500 to -100,0 on Mechanical 1
0,5600 to 4500,5600 on Mechanical 1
